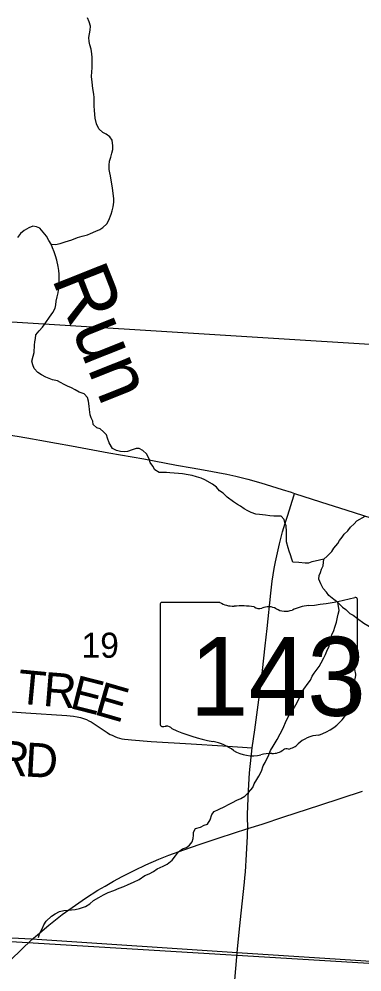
# Model space of a CAD drawing. Extents: x -8.2 to 34, y 0 to 22.
# Drawn here: x 6.718 to 7.291, y 15.452 to 17.043 of the extents above; entities that cross this region are included whole.
import ezdxf

# ---------------------------------------------------------------- set-up
doc = ezdxf.new("R2010")
doc.units = 0
for name, color, linetype in [('GM_X_Corporation', 7, 'Continuous'), ('GM_X_Minor_River', 7, 'Continuous'), ('GM_X_Minor_River_Text', 7, 'Continuous'), ('GM_X_Section_Text', 7, 'Continuous'), ('GM_X_State_Location', 7, 'Continuous'), ('GM_X_State_Route', 7, 'Continuous'), ('GM_X_State_Shield', 7, 'Continuous'), ('GM_X_Township_Road', 7, 'Continuous'), ('GM_X_Township_Road_Text', 7, 'Continuous'), ('GM_X_Township_Text', 7, 'Continuous'), ('GM_X_US_Route', 7, 'Continuous')]:
    doc.layers.add(name, color=color, linetype=linetype)

msp = doc.modelspace()

# ---------------------------------------------------------------- linework, layer by layer
at = {"layer": 'GM_X_Corporation'}
for points in [[(6.3752, 16.558), (7.4018, 16.494), (7.4044, 16.4939), (7.3299, 15.4643), (6.2993, 15.5265)], [(4.1481, 14.1), (8.9, 14.1), (8.9, 15.3663), (8.5054, 15.392), (7.8479, 15.4343), (7.082, 15.4841), (6.7558, 15.5053), (6.7389, 15.5064), (6.2987, 15.5287), (5.4088, 15.5882), (4.4836, 15.6492), (4.4152, 15.6505), (4.2922, 15.6569), (4.2674, 15.658), (4.2558, 15.6585), (4.2352, 15.4906), (4.2113, 15.0848), (4.1846, 14.6878), (4.1741, 14.5315), (4.1604, 14.3288)]]:
    msp.add_lwpolyline(points, close=True, dxfattribs=at)
at = {"layer": 'GM_X_Minor_River'}
for points in [[(6.7711, 16.667), (6.7787, 16.6669), (6.7863, 16.6684), (6.7947, 16.6713), (6.8004, 16.6728), (6.8061, 16.6746), (6.8157, 16.6783), (6.8233, 16.6805), (6.8321, 16.6831), (6.8374, 16.6849), (6.8462, 16.6887), (6.8527, 16.6916), (6.858, 16.695), (6.8645, 16.701), (6.8676, 16.7074), (6.8715, 16.7173), (6.8731, 16.723), (6.8751, 16.7294), (6.8759, 16.7374), (6.876, 16.7427), (6.8753, 16.7522), (6.8739, 16.761), (6.8728, 16.7678), (6.8717, 16.7739), (6.8706, 16.7811), (6.8695, 16.7865), (6.8685, 16.7922), (6.8681, 16.799), (6.869, 16.8059), (6.8713, 16.8123), (6.8729, 16.8191), (6.8745, 16.8256), (6.8745, 16.8316), (6.8735, 16.8408), (6.8697, 16.8465), (6.8633, 16.8511), (6.8576, 16.8535), (6.8513, 16.8596), (6.8471, 16.868), (6.845, 16.8776), (6.8436, 16.8905), (6.8433, 16.8985), (6.8434, 16.9122), (6.8427, 16.9179), (6.8413, 16.9274), (6.8398, 16.9376), (6.8388, 16.9472), (6.8393, 16.9551), (6.8397, 16.9616), (6.8402, 16.97), (6.8402, 16.9791), (6.8392, 16.9852), (6.8381, 16.9928), (6.8363, 17), (6.8348, 17.0057), (6.8345, 17.0122), (6.8357, 17.0183), (6.8369, 17.0247), (6.8373, 17.0315), (6.8351, 17.0388), (6.8321, 17.0453)], [(6.7781, 16.5601), (6.7793, 16.5658), (6.7801, 16.5719), (6.7817, 16.5791), (6.7833, 16.5859), (6.7845, 16.595), (6.7849, 16.6023), (6.7846, 16.6095), (6.7847, 16.6171), (6.7844, 16.6235), (6.7833, 16.63), (6.7807, 16.6407), (6.7785, 16.6479), (6.7767, 16.6544), (6.7737, 16.6613), (6.7715, 16.6674), (6.7678, 16.6731), (6.7637, 16.6808), (6.758, 16.6873), (6.7528, 16.6938), (6.7471, 16.6961), (6.7406, 16.6973), (6.7341, 16.6947), (6.7261, 16.6903), (6.72, 16.685), (6.7154, 16.6786)], [(7.2269, 16.1413), (7.2125, 16.138), (7.2071, 16.1366), (7.2014, 16.1347), (7.1957, 16.1344), (7.1851, 16.1357), (7.1752, 16.1361), (7.1737, 16.1415), (7.1715, 16.1483), (7.1689, 16.1545), (7.1675, 16.1602), (7.1645, 16.1701), (7.1647, 16.1872), (7.164, 16.1967), (7.1618, 16.2024), (7.1607, 16.2077), (7.1558, 16.2131), (7.1493, 16.2132), (7.1436, 16.2129), (7.1368, 16.2137), (7.1296, 16.2145), (7.1194, 16.2158), (7.1133, 16.2166), (7.1057, 16.2193), (7.1, 16.2217), (7.0936, 16.2251), (7.088, 16.2298), (7.0827, 16.2325), (7.0762, 16.2367), (7.0657, 16.2448), (7.0589, 16.2513), (7.0529, 16.2556), (7.0476, 16.2613), (7.0412, 16.2667), (7.0284, 16.2737), (7.0223, 16.2764), (7.014, 16.2788), (7.0071, 16.2808), (7.0003, 16.2823), (6.9908, 16.2836), (6.9844, 16.2844), (6.9699, 16.2853), (6.9639, 16.2858), (6.9582, 16.2862), (6.9517, 16.2859), (6.9449, 16.2905), (6.9412, 16.2966), (6.9371, 16.3028), (6.9352, 16.3089), (6.9307, 16.3169), (6.9247, 16.3226), (6.9187, 16.3261), (6.9134, 16.3262), (6.9069, 16.3236), (6.8989, 16.321), (6.8932, 16.3207), (6.8871, 16.3211), (6.8806, 16.3227), (6.8738, 16.3262), (6.8682, 16.3354), (6.8656, 16.3434), (6.8638, 16.3487), (6.8589, 16.3541), (6.8533, 16.3587), (6.8476, 16.3607), (6.8415, 16.3661), (6.8408, 16.3718), (6.8382, 16.3771), (6.8364, 16.3824), (6.8353, 16.3912), (6.835, 16.3969), (6.8339, 16.4053), (6.8321, 16.411), (6.8265, 16.4171), (6.8181, 16.4203), (6.8117, 16.4241), (6.8053, 16.4272), (6.7985, 16.43), (6.7932, 16.4331), (6.7871, 16.4365), (6.7818, 16.4389), (6.7739, 16.4409), (6.7682, 16.4428), (6.7625, 16.4451), (6.7553, 16.449), (6.7493, 16.4529), (6.7429, 16.4598), (6.7407, 16.4655), (6.7392, 16.472), (6.7412, 16.4803), (6.7428, 16.4864), (6.7437, 16.4985), (6.7441, 16.5039), (6.7453, 16.5099), (6.7461, 16.516), (6.7515, 16.5224), (6.7572, 16.5284), (6.7623, 16.5364), (6.7688, 16.5454), (6.7742, 16.553), (6.7781, 16.5601)], [(7.2191, 16.1137), (7.2214, 16.119), (7.223, 16.1243), (7.2257, 16.1303), (7.2265, 16.136), (7.2269, 16.1413), (7.2327, 16.1462), (7.2403, 16.1541), (7.2438, 16.1598), (7.2504, 16.1673), (7.2534, 16.1726), (7.2577, 16.1779), (7.2611, 16.1832), (7.2669, 16.1888), (7.2715, 16.1944), (7.2776, 16.2001), (7.2823, 16.2054), (7.2961, 16.2129)], [(6.7504, 15.5097), (6.752, 15.5153), (6.7563, 15.524), (6.7594, 15.5305), (6.7629, 15.5369), (6.7721, 15.5452), (6.7782, 15.5489), (6.7854, 15.5526), (6.7927, 15.5545), (6.7995, 15.5551), (6.8113, 15.5562), (6.8189, 15.558), (6.8288, 15.5613), (6.8361, 15.5658), (6.8422, 15.5714), (6.851, 15.5763), (6.859, 15.5808), (6.8667, 15.5845), (6.8762, 15.5878), (6.885, 15.5919), (6.8926, 15.5948), (6.8999, 15.5982), (6.909, 15.6019), (6.9185, 15.6064), (6.9277, 15.6127), (6.9354, 15.6157), (6.9426, 15.6198), (6.9487, 15.6243), (6.9583, 15.6284), (6.9655, 15.6321), (6.9736, 15.6385), (6.979, 15.646), (6.9843, 15.6524), (6.9909, 15.6577), (6.9973, 15.6599), (7.0027, 15.6636), (7.0069, 15.6693), (7.0089, 15.675), (7.0093, 15.6803), (7.0094, 15.6856), (7.0125, 15.6917), (7.0212, 15.6939), (7.0273, 15.6968), (7.0327, 15.6987), (7.0369, 15.7062), (7.04, 15.7146), (7.0435, 15.7198), (7.0511, 15.7232), (7.0618, 15.728), (7.0676, 15.7314), (7.0744, 15.7347), (7.0817, 15.7388), (7.0882, 15.7414), (7.0951, 15.7452), (7.1012, 15.7516), (7.1081, 15.7598), (7.1104, 15.7659), (7.1151, 15.7731), (7.1182, 15.7791), (7.1228, 15.7871), (7.1256, 15.7962), (7.129, 15.8014), (7.1352, 15.8147), (7.138, 15.8219), (7.1422, 15.829), (7.1488, 15.84), (7.1588, 15.8589), (7.1639, 15.871), (7.1701, 15.8827), (7.1755, 15.8903), (7.1801, 15.8982), (7.1859, 15.9088), (7.1898, 15.9182), (7.1937, 15.9239), (7.201, 15.9341), (7.2045, 15.9394), (7.2076, 15.9458), (7.2106, 15.9511), (7.2191, 15.962), (7.2226, 15.9681), (7.2269, 15.9764), (7.2296, 15.9821), (7.2319, 15.9877), (7.2358, 15.9961), (7.2378, 16.0044), (7.2401, 16.015), (7.2436, 16.0222), (7.2452, 16.0275), (7.2483, 16.0358), (7.2499, 16.0442), (7.2511, 16.0495), (7.2523, 16.0556), (7.2516, 16.0628), (7.2505, 16.0689), (7.2438, 16.0739), (7.2351, 16.0808), (7.2313, 16.0862), (7.2261, 16.0923), (7.222, 16.0999), (7.2186, 16.108), (7.2191, 16.1137)], [(7.2503, 16.069), (7.2584, 16.0612), (7.2637, 16.057), (7.2705, 16.0504), (7.2762, 16.0477), (7.2833, 16.0419), (7.2935, 16.0342), (7.3069, 16.0267)]]:
    msp.add_lwpolyline(points, dxfattribs=at)
at = {"layer": 'GM_X_State_Route'}
for points in [[(7.0998, 15.6914), (7.0996, 15.7121), (7.0996, 15.7153), (7.1012, 15.7547), (7.103, 15.7844), (7.1074, 15.8259), (7.1115, 15.8563), (7.1206, 15.9228), (7.122, 15.9345), (7.129, 15.9963), (7.1325, 16.0253), (7.1386, 16.0845), (7.1409, 16.1043), (7.1441, 16.1258), (7.1449, 16.1312), (7.146, 16.1368), (7.1471, 16.142), (7.1529, 16.167), (7.158, 16.1866), (7.1624, 16.2014), (7.1666, 16.2146), (7.1769, 16.2469), (7.1782, 16.251)], [(6.7391, 15.5059), (6.7487, 15.5141), (6.7676, 15.5302), (6.7899, 15.5476), (6.8119, 15.5636), (6.8287, 15.575), (6.8496, 15.5882), (6.8615, 15.5954), (6.8758, 15.6034), (6.8902, 15.6113), (6.9115, 15.622), (6.9298, 15.6306), (6.9515, 15.6402), (6.9681, 15.6469), (6.9929, 15.656), (7.0205, 15.6653), (7.0523, 15.6757), (7.0998, 15.6914), (7.1238, 15.6989), (7.1604, 15.7108), (7.2201, 15.7306), (7.2917, 15.7539)], [(7.0822, 15.4836), (7.0833, 15.4961), (7.0864, 15.5291), (7.0887, 15.5503), (7.0943, 15.6016), (7.0951, 15.6088), (7.0956, 15.6142), (7.096, 15.6193), (7.0975, 15.6478), (7.0992, 15.6787), (7.0996, 15.6849), (7.0998, 15.6914)], [(6.671, 15.4354), (6.7039, 15.472), (6.7391, 15.5059)], [(6.7476, 14.8327), (6.7629, 14.8542), (6.7898, 14.8906), (6.8166, 14.9279), (6.8432, 14.962), (6.8591, 14.9796), (6.8687, 14.9899), (6.9461, 15.0632), (7.0087, 15.1252), (7.0358, 15.1494), (7.0486, 15.1622), (7.0541, 15.1711), (7.0585, 15.1816), (7.0614, 15.1979), (7.0661, 15.269), (7.075, 15.3989), (7.0822, 15.4836)]]:
    msp.add_lwpolyline(points, dxfattribs=at)
at = {"layer": 'GM_X_State_Shield'}
for p, q in [((7.2831, 15.9693), (7.2831, 16.074)), ((6.9535, 16.0656), (6.9535, 15.8655)), ((7.0533, 16.0691), (6.9567, 16.0691)), ((7.283, 15.9694), (7.2831, 15.9693))]:
    msp.add_line(p, q, dxfattribs=at)
for centre, major_axis, start_param, end_param in [((7.1657, 16.3419), (0.3495, 0), 4.814394, 5.042369), ((7.2794, 16.0745), (0.00367, 0), 6.141152, 7.989035), ((6.9573, 16.066), (0.00382, 0), 1.712693, 3.28349), ((7.0762, 16.0923), (0.037, 0), 4.042523, 4.731795), ((7.0885, 15.9567), (0.133, 0), 1.404758, 1.657858), ((7.1187, 16.0671), (0.0107, 0), 3.836095, 5.185415), ((7.1344, 16.044), (0.0222, 0), 0.950623, 2.079405), ((7.1631, 16.0757), (0.0267, 0), 4.081561, 5.145723), ((7.2103, 16.0079), (0.0703, 0), 1.699011, 2.107814), ((7.2822, 15.9617), (0.00568, 0), 1.883978, 3.671073), ((7.2792, 15.9689), (0.00393, 0), 5.05454, 6.418171), ((7.2461, 15.9484), (0.0341, 0), 5.934695, 6.695948), ((7.2962, 15.9255), (0.0248, 0), 2.387724, 3.262537), ((7.1852, 15.9122), (0.0874, 0), 5.101752, 6.440018), ((6.9573, 15.8651), (0.00385, 0), 3.00124, 4.508301), ((6.9579, 15.8855), (0.0294, 0), 4.665946, 4.897461), ((6.9639, 15.854), (0.0106, 0), 0.519207, 1.627899), ((7.0977, 16.0338), (0.2524, 0), 4.195997, 4.488961), ((7.0225, 15.7756), (0.079, 0), 0.823519, 1.323587), ((7.2221, 15.8093), (0.0479, 0), 1.647645, 2.488434), ((7.1079, 15.853), (0.0501, 0), 4.026481, 4.996735), ((7.1405, 15.838), (0.0267, 0), 4.691044, 5.507374), ((7.1647, 15.8186), (0.00752, 0), 1.147584, 2.315152), ((7.1614, 15.8461), (0.0282, 0), 4.937069, 5.64225), ((7.1368, 15.7838), (0.0412, 0), 1.495662, 1.94098)]:
    msp.add_ellipse(centre, major_axis=major_axis, ratio=0.8, start_param=start_param, end_param=end_param, dxfattribs=at)
at = {"layer": 'GM_X_Township_Road'}
msp.add_lwpolyline([(6.6511, 15.8902), (6.7293, 15.8844), (6.7979, 15.8799), (6.8033, 15.8795), (6.809, 15.8789), (6.815, 15.8779), (6.8204, 15.8767), (6.8257, 15.8751), (6.8305, 15.8732), (6.8343, 15.8714), (6.8381, 15.8696), (6.8417, 15.8675), (6.8468, 15.8641), (6.8648, 15.8518), (6.8673, 15.8502), (6.8703, 15.8486), (6.8732, 15.8472), (6.878, 15.845), (6.882, 15.8434), (6.8857, 15.8423), (6.8897, 15.8414), (6.8941, 15.8407), (6.9001, 15.8399), (6.9056, 15.8394), (6.9383, 15.8369), (7.0051, 15.8326), (7.0585, 15.8294), (7.1074, 15.8259)], dxfattribs=at)
at = {"layer": 'GM_X_Township_Text'}
msp.add_lwpolyline([(8.9, 15.3663), (8.5054, 15.392), (7.8479, 15.4343), (7.082, 15.4841), (6.7558, 15.5053), (6.7389, 15.5064), (6.2987, 15.5287), (5.4088, 15.5882), (4.4836, 15.6492), (4.4152, 15.6505), (4.2922, 15.6569), (4.2674, 15.658), (4.2558, 15.6585), (4.2352, 15.4906), (4.2113, 15.0848), (4.1846, 14.6878), (4.1741, 14.5315), (4.1604, 14.3288), (4.1481, 14.1)], dxfattribs=at)
at = {"layer": 'GM_X_US_Route'}
msp.add_lwpolyline([(6.6937, 16.3502), (6.7181, 16.3459), (6.7402, 16.3419), (6.7524, 16.3397), (6.7805, 16.3348), (6.8056, 16.3303), (6.8679, 16.3189), (6.926, 16.3086), (6.9809, 16.2983), (7.0072, 16.2937), (7.0262, 16.2904), (7.0647, 16.2832), (7.0799, 16.28), (7.0998, 16.275), (7.1219, 16.2687), (7.1576, 16.2577), (7.1724, 16.2529), (7.1782, 16.251), (7.2214, 16.2371), (7.2652, 16.2231), (7.3054, 16.21)], dxfattribs=at)

# ---------------------------------------------------------------- texts
at = {"layer": 'GM_X_Minor_River_Text'}
msp.add_text('Run', height=0.09471, rotation=291.6912, dxfattribs=at).set_placement((6.7719, 16.6103))
at = {"layer": 'GM_X_Section_Text'}
msp.add_text('19', height=0.04186, rotation=0, dxfattribs=at).set_placement((6.8223, 15.9766))
at = {"layer": 'GM_X_State_Location'}
for s in ['s', 'r']:
    msp.add_text(s, height=0.000189, dxfattribs=at).set_placement((7.1146, 15.9523))
msp.add_text('143', height=0.000189, rotation=0, dxfattribs=at).set_placement((7.0477, 15.9385))
at = {"layer": 'GM_X_State_Shield'}
msp.add_text('143', height=0.13184, dxfattribs=at).set_placement((7.003, 15.8796))
at = {"layer": 'GM_X_Township_Road_Text'}
for s, rotation, p in [('T', 354.6017, (6.7135, 15.9005)), ('R', 355.3737, (6.7566, 15.8964)), ('E', 345.7496, (6.8007, 15.893)), ('E', 343.8845, (6.8414, 15.8827)), ('R', 354.0393, (6.6773, 15.7836)), ('D', 356.7776, (6.7266, 15.7785))]:
    msp.add_text(s, height=0.0568, rotation=rotation, dxfattribs=at).set_placement(p)

doc.saveas('drawing.dxf')
